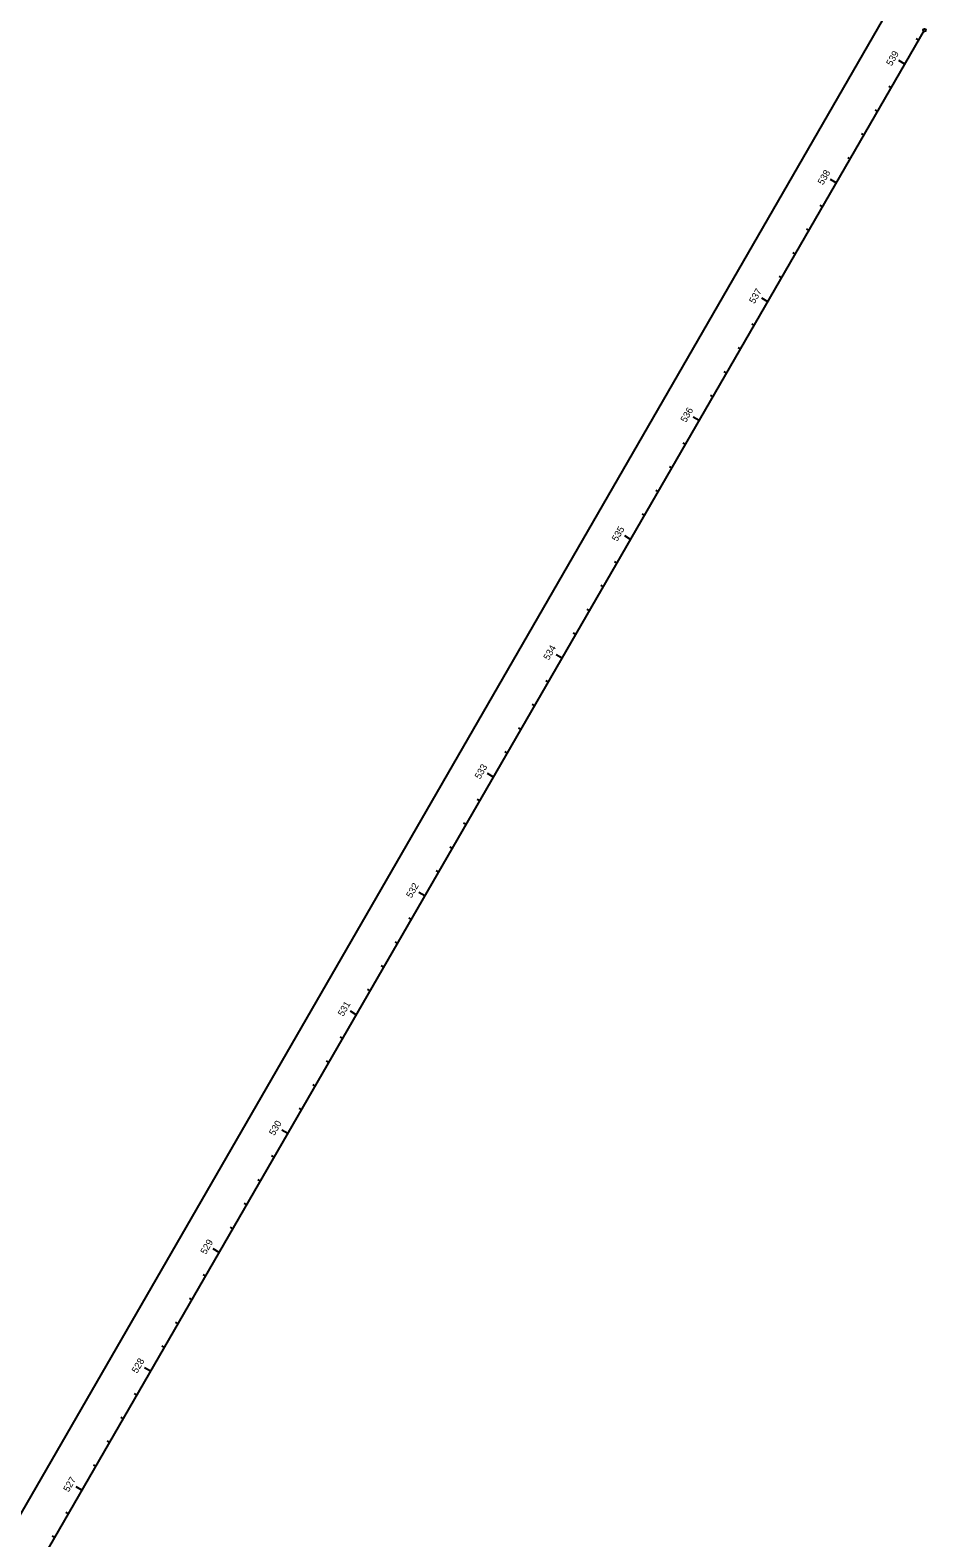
# Model space of a CAD drawing. Extents: x 2003883 to 2007688, y 399149 to 412300.
# Drawn here: x 2005443 to 2006096, y 400266 to 401364 of the extents above; entities that cross this region are included whole.
import ezdxf

# ---------------------------------------------------------------- set-up
doc = ezdxf.new("R2010")
doc.units = 0
for name, color, linetype in [('BaselineSurvey', 7, 'Continuous'), ('ConstLines', 7, 'Continuous'), ('Default', 7, 'Continuous'), ('TextAlgnCardinalPnt', 7, 'Continuous'), ('TextAlgnStation100', 7, 'Continuous'), ('TextAlgnStation1000', 7, 'Continuous'), ('TextAlgnStation500', 7, 'Continuous'), ('TextAlgnTicks100', 7, 'Continuous'), ('TextAlgnTicks1000', 7, 'Continuous'), ('TextAlgnTicks500', 7, 'Continuous'), ('TextAlgnTicks5000', 7, 'Continuous')]:
    doc.layers.add(name, color=color, linetype=linetype)

msp = doc.modelspace()

# ---------------------------------------------------------------- linework, layer by layer
at = {"layer": 'BaselineSurvey'}
msp.add_line((2004815.7, 399149), (2006095.1, 401364.2), dxfattribs=at)
at = {"layer": 'ConstLines'}
msp.add_line((2004789.7, 399164), (2006069.1, 401379.2), dxfattribs=at)
at = {"layer": 'Default'}
msp.add_line((2004815.7, 399149), (2006095.1, 401364.2), dxfattribs=at)
at = {"layer": 'TextAlgnCardinalPnt'}
msp.add_circle((2006095.1, 401364.2), 1, dxfattribs=at)
at = {"layer": 'TextAlgnTicks100'}
for p, q in [((2006090.8, 401356.9), (2006089.1, 401357.9)), ((2006080.8, 401339.5), (2006076.5, 401342)), ((2006070.8, 401322.2), (2006069.1, 401323.2)), ((2006060.8, 401304.9), (2006059.1, 401305.9)), ((2006050.8, 401287.6), (2006049.1, 401288.6)), ((2006040.8, 401270.3), (2006039.1, 401271.3)), ((2006030.8, 401252.9), (2006026.5, 401255.4)), ((2006020.8, 401235.6), (2006019.1, 401236.6)), ((2006010.8, 401218.3), (2006009.1, 401219.3)), ((2006000.8, 401201), (2005999.1, 401202)), ((2005990.8, 401183.7), (2005989.1, 401184.7)), ((2005980.8, 401166.3), (2005976.5, 401168.9)), ((2005970.8, 401149), (2005969.1, 401150)), ((2005960.8, 401131.7), (2005959.1, 401132.7)), ((2005950.8, 401114.4), (2005949.1, 401115.4)), ((2005940.8, 401097.1), (2005939.1, 401098.1)), ((2005930.8, 401079.8), (2005926.5, 401082.3)), ((2005920.8, 401062.4), (2005919.1, 401063.4)), ((2005910.8, 401045.1), (2005909.1, 401046.1)), ((2005900.8, 401027.8), (2005899.1, 401028.8)), ((2005890.8, 401010.5), (2005889.1, 401011.5)), ((2005880.8, 400993.2), (2005876.5, 400995.7)), ((2005870.8, 400975.8), (2005869.1, 400976.8)), ((2005860.8, 400958.5), (2005859.1, 400959.5)), ((2005850.8, 400941.2), (2005849.1, 400942.2)), ((2005840.8, 400923.9), (2005839, 400924.9)), ((2005830.8, 400906.6), (2005826.4, 400909.1)), ((2005820.8, 400889.2), (2005819, 400890.2)), ((2005810.8, 400871.9), (2005809, 400872.9)), ((2005800.8, 400854.6), (2005799, 400855.6)), ((2005790.8, 400837.3), (2005789, 400838.3)), ((2005780.8, 400820), (2005776.4, 400822.5)), ((2005770.8, 400802.7), (2005769, 400803.7)), ((2005760.8, 400785.3), (2005759, 400786.3)), ((2005750.8, 400768), (2005749, 400769)), ((2005740.8, 400750.7), (2005739, 400751.7)), ((2005730.8, 400733.4), (2005726.4, 400735.9)), ((2005720.7, 400716.1), (2005719, 400717.1)), ((2005710.7, 400698.7), (2005709, 400699.7)), ((2005700.7, 400681.4), (2005699, 400682.4)), ((2005690.7, 400664.1), (2005689, 400665.1)), ((2005680.7, 400646.8), (2005676.4, 400649.3)), ((2005670.7, 400629.5), (2005669, 400630.5)), ((2005660.7, 400612.1), (2005659, 400613.1)), ((2005650.7, 400594.8), (2005649, 400595.8)), ((2005640.7, 400577.5), (2005639, 400578.5)), ((2005630.7, 400560.2), (2005626.4, 400562.7)), ((2005620.7, 400542.9), (2005619, 400543.9)), ((2005610.7, 400525.5), (2005609, 400526.5)), ((2005600.7, 400508.2), (2005599, 400509.2)), ((2005590.7, 400490.9), (2005589, 400491.9)), ((2005580.7, 400473.6), (2005576.4, 400476.1)), ((2005570.7, 400456.3), (2005569, 400457.3)), ((2005560.7, 400439), (2005559, 400440)), ((2005550.7, 400421.6), (2005549, 400422.6)), ((2005540.7, 400404.3), (2005539, 400405.3)), ((2005530.7, 400387), (2005526.4, 400389.5)), ((2005520.7, 400369.7), (2005519, 400370.7)), ((2005510.7, 400352.4), (2005509, 400353.4)), ((2005500.7, 400335), (2005499, 400336)), ((2005490.7, 400317.7), (2005489, 400318.7)), ((2005480.7, 400300.4), (2005476.4, 400302.9)), ((2005470.7, 400283.1), (2005468.9, 400284.1)), ((2005460.7, 400265.8), (2005458.9, 400266.8))]:
    msp.add_line(p, q, dxfattribs=at)
at = {"layer": 'TextAlgnTicks1000'}
for p, q in [((2006030.8, 401252.9), (2006029.1, 401253.9)), ((2005930.8, 401079.8), (2005929.1, 401080.8)), ((2005830.8, 400906.6), (2005829, 400907.6)), ((2005730.8, 400733.4), (2005729, 400734.4)), ((2005630.7, 400560.2), (2005626.4, 400562.7)), ((2005530.7, 400387), (2005529, 400388))]:
    msp.add_line(p, q, dxfattribs=at)
at = {"layer": 'TextAlgnTicks500'}
for p, q in [((2006080.8, 401339.5), (2006079.1, 401340.5)), ((2006030.8, 401252.9), (2006029.1, 401253.9)), ((2005980.8, 401166.3), (2005979.1, 401167.4)), ((2005930.8, 401079.8), (2005929.1, 401080.8)), ((2005880.8, 400993.2), (2005876.5, 400995.7)), ((2005830.8, 400906.6), (2005829, 400907.6)), ((2005780.8, 400820), (2005779, 400821)), ((2005730.8, 400733.4), (2005729, 400734.4)), ((2005680.7, 400646.8), (2005679, 400647.8)), ((2005630.7, 400560.2), (2005626.4, 400562.7)), ((2005580.7, 400473.6), (2005579, 400474.6)), ((2005530.7, 400387), (2005529, 400388)), ((2005480.7, 400300.4), (2005479, 400301.4))]:
    msp.add_line(p, q, dxfattribs=at)
at = {"layer": 'TextAlgnTicks5000'}
msp.add_line((2005630.7, 400560.2), (2005629, 400561.2), dxfattribs=at)

# ---------------------------------------------------------------- texts
at = {"layer": 'TextAlgnStation100'}
for s, p in [('539', (2006071.1, 401337.7)), ('538', (2006021.1, 401251)), ('537', (2005971.1, 401164.5)), ('536', (2005921.1, 401077.9)), ('535', (2005871, 400991.2)), ('534', (2005821.1, 400904.7)), ('533', (2005771, 400818)), ('532', (2005721, 400731.4)), ('531', (2005671.2, 400645.2)), ('530', (2005621, 400558.3)), ('529', (2005571, 400471.7)), ('528', (2005520.9, 400385.1)), ('527', (2005471, 400298.6))]:
    msp.add_text(s, height=4.98, rotation=59.9911, dxfattribs=at).set_placement(p)
at = {"layer": 'TextAlgnStation1000'}
msp.add_text('530', height=4.98, rotation=59.9911, dxfattribs=at).set_placement((2005621, 400558.3))
at = {"layer": 'TextAlgnStation500'}
for s, p in [('535', (2005871, 400991.2)), ('530', (2005621, 400558.3))]:
    msp.add_text(s, height=4.98, rotation=59.9911, dxfattribs=at).set_placement(p)

doc.saveas('drawing.dxf')
